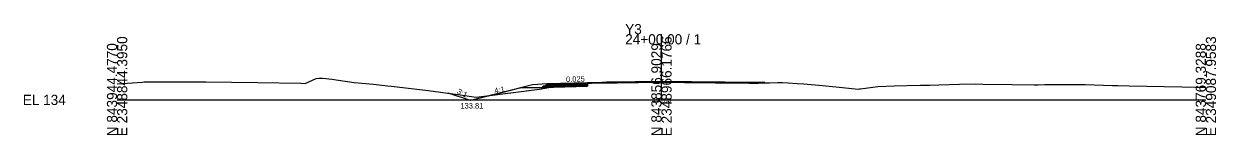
# Model space of a CAD drawing. Extents: x -26 to 2349107, y -10 to 844057.
# Drawn here: x -25.7 to 302.8, y 2990.3 to 3020.9 of the extents above; entities that cross this region are included whole.
import ezdxf

# ---------------------------------------------------------------- set-up
doc = ezdxf.new("R2010")
doc.units = 0
for name, color, linetype in [('Exist Cross Section Cell', 7, 'Continuous'), ('Exist XS Center Line Elevation Label', 7, 'Continuous'), ('Exist XS Ground Line', 7, 'Continuous'), ('Prop CMT Pvmt Course 1', 7, 'Continuous'), ('Prop CMT Pvmt Course 2', 7, 'Continuous'), ('Prop CMT Pvmt Course 3', 7, 'Continuous'), ('Prop CMT Pvmt Surface Shoulder', 7, 'Continuous'), ('Prop CMT Shld Paved Course 1', 7, 'Continuous'), ('Prop CMT Shld Paved Course 2', 7, 'Continuous'), ('Prop CMT Shld Paved Course 3', 7, 'Continuous'), ('Prop CMT Slope Grass', 7, 'Continuous'), ('Prop CMT Subgrade Earthwork', 7, 'Continuous'), ('Prop XS Ditch Standard Text', 7, 'Continuous'), ('Prop XS Earthwork Shape', 7, 'Continuous'), ('Prop XS SE Text', 7, 'Continuous'), ('Prop XS Side Slope Text', 7, 'Continuous')]:
    doc.layers.add(name, color=color, linetype=linetype)

msp = doc.modelspace()

# ---------------------------------------------------------------- linework, layer by layer
at = {"layer": 'Exist Cross Section Cell'}
for p, q in [((150, 3000), (150, 3018.07)), ((0, 3000), (150, 3000)), ((150, 3000), (300, 3000))]:
    msp.add_line(p, q, dxfattribs=at)
at = {"layer": 'Exist XS Ground Line'}
msp.add_lwpolyline([(0, 3004.39), (7, 3004.92), (7.42, 3004.94), (19.2, 3004.98), (24.55, 3004.95), (31.57, 3004.84), (38.78, 3004.75), (50.6, 3004.62), (51.84, 3004.55), (54.83, 3005.93), (55.64, 3005.99), (56.64, 3006.02), (57.54, 3005.9), (59.2, 3005.68), (61.01, 3005.41), (65.28, 3004.76), (70.67, 3004.33), (74.47, 3003.9), (75.65, 3003.75), (85.74, 3002.58), (94.49, 3001.4), (98.97, 3000.76), (116.35, 3002.99), (120.98, 3003.81), (127.35, 3004.48), (129.61, 3004.57), (130.73, 3004.6), (133.63, 3004.68), (134.19, 3004.71), (134.97, 3004.71), (136.7, 3004.72), (137.78, 3004.73), (139.21, 3004.77), (139.81, 3004.78), (141.35, 3004.8), (142.88, 3004.81), (143.57, 3004.82), (144.94, 3004.84), (145.94, 3004.85), (147.1, 3004.85), (148.02, 3004.85), (148.62, 3004.87), (149.89, 3004.86), (151.13, 3004.86), (152.61, 3004.85), (153.89, 3004.85), (155.17, 3004.84), (156.36, 3004.83), (157.45, 3004.82), (158.24, 3004.82), (160.61, 3004.8), (161.34, 3004.79), (163.22, 3004.76), (164.91, 3004.73), (166.43, 3004.72), (167.49, 3004.72), (169.18, 3004.71), (170.55, 3004.7), (173.62, 3004.65), (174.14, 3004.63), (174.66, 3004.63), (176.77, 3004.64), (177.19, 3004.65), (177.77, 3004.66), (178.95, 3004.68), (179.79, 3004.72), (182.05, 3004.79), (182.76, 3004.79), (183.39, 3004.74), (184.9, 3004.65), (187.39, 3004.49), (189.2, 3004.41), (194.33, 3003.95), (197.13, 3003.71), (198.11, 3003.61), (204.16, 3002.99), (204.56, 3003.04), (204.87, 3003.07), (209.62, 3003.67), (214.12, 3003.84), (221.4, 3004.02), (223.94, 3004.09), (226.42, 3004.16), (232.08, 3004.36), (236.58, 3004.4), (238.58, 3004.36), (246.51, 3004.22), (252.72, 3004.15), (253.77, 3004.17), (255.64, 3004.22), (266.78, 3004.19), (274.26, 3003.95), (275.05, 3003.95), (275.74, 3003.95), (278.88, 3003.91), (293.35, 3003.59), (297.14, 3003.47), (300, 3003.46)], dxfattribs=at)
at = {"layer": 'Prop CMT Pvmt Course 1'}
for p, q in [((122.5, 3004.52), (122.5, 3004.27)), ((129.61, 3004.7), (129.61, 3004.45))]:
    msp.add_line(p, q, dxfattribs=at)
at = {"layer": 'Prop CMT Pvmt Course 2'}
for p, q in [((122.5, 3004.27), (122.5, 3003.93)), ((129.61, 3004.45), (129.61, 3004.11))]:
    msp.add_line(p, q, dxfattribs=at)
at = {"layer": 'Prop CMT Pvmt Course 3'}
for p, q in [((122.5, 3003.93), (122.5, 3003.56)), ((129.61, 3004.11), (129.61, 3003.74))]:
    msp.add_line(p, q, dxfattribs=at)
at = {"layer": 'Prop CMT Pvmt Surface Shoulder'}
for p, q in [((129.61, 3004.7), (118.5, 3004.42)), ((178.49, 3004.8), (178.49, 3004.67))]:
    msp.add_line(p, q, dxfattribs=at)
msp.add_lwpolyline([(129.61, 3004.7), (130.73, 3004.73), (133.62, 3004.81), (134.19, 3004.83), (134.97, 3004.84), (136.7, 3004.85), (137.78, 3004.85), (139.21, 3004.89), (139.81, 3004.91), (141.35, 3004.92), (142.88, 3004.94), (143.57, 3004.95), (144.94, 3004.96), (145.94, 3004.98), (147.1, 3004.98), (148.02, 3004.97), (148.62, 3005), (149.89, 3004.98), (151.13, 3004.99), (152.61, 3004.98), (153.89, 3004.98), (155.17, 3004.97), (156.36, 3004.96), (157.45, 3004.95), (158.24, 3004.94), (160.61, 3004.92), (161.34, 3004.92), (163.22, 3004.88), (164.91, 3004.86), (166.43, 3004.84), (167.49, 3004.84), (169.18, 3004.83), (170.55, 3004.83), (173.62, 3004.78), (174.15, 3004.76), (174.66, 3004.76), (176.77, 3004.76), (177.18, 3004.77), (177.76, 3004.79), (178.49, 3004.8)], dxfattribs=at)
at = {"layer": 'Prop CMT Shld Paved Course 1'}
for p, q in [((118.24, 3004.16), (129.61, 3004.45)), ((118.5, 3004.42), (118.24, 3004.16)), ((129.61, 3004.7), (118.5, 3004.42)), ((122.5, 3004.27), (122.5, 3004.52)), ((129.61, 3004.45), (129.61, 3004.7))]:
    msp.add_line(p, q, dxfattribs=at)
at = {"layer": 'Prop CMT Shld Paved Course 2'}
for p, q in [((118.24, 3004.16), (117.9, 3003.82)), ((117.9, 3003.82), (129.61, 3004.11)), ((129.61, 3004.45), (118.24, 3004.16)), ((122.5, 3003.93), (122.5, 3004.27)), ((129.61, 3004.11), (129.61, 3004.45))]:
    msp.add_line(p, q, dxfattribs=at)
at = {"layer": 'Prop CMT Shld Paved Course 3'}
for p, q in [((117.4, 3003.81), (117.02, 3003.42)), ((117.1, 3003.42), (129.61, 3003.74)), ((117.9, 3003.82), (117.4, 3003.81)), ((129.61, 3004.11), (117.9, 3003.82)), ((122.5, 3003.56), (122.5, 3003.93)), ((129.61, 3003.74), (129.61, 3004.11))]:
    msp.add_line(p, q, dxfattribs=at)
at = {"layer": 'Prop CMT Slope Grass'}
for p, q in [((114.5, 3004.1), (97.35, 2999.81)), ((118.5, 3004.42), (114.5, 3004.1)), ((97.35, 2999.81), (91.26, 3001.84))]:
    msp.add_line(p, q, dxfattribs=at)
at = {"layer": 'Prop CMT Subgrade Earthwork'}
for p, q in [((117.02, 3003.42), (111.22, 3003.28)), ((129.61, 3003.74), (117.02, 3003.42)), ((129.61, 3003.74), (129.61, 3004.57))]:
    msp.add_line(p, q, dxfattribs=at)
at = {"layer": 'Prop XS Earthwork Shape'}
for points in [[(103.44, 3001.33), (116.35, 3002.99), (119.07, 3003.47), (117.02, 3003.42), (111.22, 3003.28)], [(119.07, 3003.47), (120.98, 3003.81), (127.35, 3004.48), (129.61, 3004.57), (130.73, 3004.6), (133.63, 3004.68), (134.19, 3004.71), (134.97, 3004.71), (136.7, 3004.72), (137.78, 3004.73), (139.21, 3004.77), (139.81, 3004.78), (141.35, 3004.8), (142.88, 3004.81), (143.57, 3004.82), (144.94, 3004.84), (145.94, 3004.85), (147.1, 3004.85), (148.02, 3004.85), (148.62, 3004.87), (149.89, 3004.86), (151.13, 3004.86), (152.61, 3004.85), (153.89, 3004.85), (155.17, 3004.84), (156.36, 3004.83), (157.45, 3004.82), (158.24, 3004.82), (160.61, 3004.8), (161.34, 3004.79), (163.22, 3004.76), (164.91, 3004.73), (166.43, 3004.72), (167.49, 3004.72), (169.18, 3004.71), (170.55, 3004.7), (173.62, 3004.65), (174.14, 3004.63), (174.66, 3004.63), (176.77, 3004.64), (177.19, 3004.65), (177.77, 3004.66), (178.49, 3004.67), (178.49, 3004.8), (177.76, 3004.79), (177.18, 3004.77), (176.77, 3004.76), (174.66, 3004.76), (174.15, 3004.76), (173.62, 3004.78), (170.55, 3004.83), (169.18, 3004.83), (167.49, 3004.84), (166.43, 3004.84), (164.91, 3004.86), (163.22, 3004.88), (161.34, 3004.92), (160.61, 3004.92), (158.24, 3004.94), (157.45, 3004.95), (156.36, 3004.96), (155.17, 3004.97), (153.89, 3004.98), (152.61, 3004.98), (151.13, 3004.99), (149.89, 3004.98), (148.62, 3005), (148.02, 3004.97), (147.1, 3004.98), (145.94, 3004.98), (144.94, 3004.96), (143.57, 3004.95), (142.88, 3004.94), (141.35, 3004.92), (139.81, 3004.91), (139.21, 3004.89), (137.78, 3004.85), (136.7, 3004.85), (134.97, 3004.84), (134.19, 3004.83), (133.62, 3004.81), (130.73, 3004.73), (129.61, 3004.7), (118.5, 3004.42), (114.5, 3004.1), (111.22, 3003.28), (117.02, 3003.42)], [(119.07, 3003.47), (120.98, 3003.81), (127.35, 3004.48), (129.61, 3004.57), (129.61, 3003.74)], [(103.44, 3001.33), (97.35, 2999.81), (91.26, 3001.84), (94.49, 3001.4), (98.97, 3000.76)]]:
    msp.add_lwpolyline(points, close=True, dxfattribs=at)

# ---------------------------------------------------------------- texts
at = {"layer": 'Exist Cross Section Cell'}
for s, p in [('Y3', (140, 3018.07)), ('24+00.00 / 1', (140, 3015.27)), ('EL 134', (-26, 2998.6))]:
    msp.add_text(s, height=2.8, dxfattribs=at).set_placement(p)
for s, p in [('E 2348844.3950', (2.8, 2990)), ('E 2348966.1766', (152.8, 2990)), ('E 2349087.9583', (302.8, 2990)), ('N 843944.4770', (0, 2990)), ('N 843856.9029', (150, 2990)), ('N 843769.3288', (300, 2990))]:
    msp.add_text(s, height=2.8, rotation=90, dxfattribs=at).set_placement(p)
at = {"layer": 'Exist XS Center Line Elevation Label'}
msp.add_text('138.86', height=1.2, dxfattribs=at).set_placement((147.52, 2999.26))
at = {"layer": 'Prop XS Ditch Standard Text'}
msp.add_text('133.81', height=1.5, dxfattribs=at).set_placement((94.59, 2997.63))
at = {"layer": 'Prop XS SE Text'}
msp.add_text('0.025', height=1.5, rotation=1.4321, dxfattribs=at).set_placement((123.71, 3004.91))
at = {"layer": 'Prop XS Side Slope Text'}
for s, rotation, p in [('3:1', 334.1575, (93.5, 3001.87)), ('4:1', 11.4513, (104.1, 3001.73))]:
    msp.add_text(s, height=1.5, rotation=rotation, dxfattribs=at).set_placement(p)

doc.saveas('drawing.dxf')
